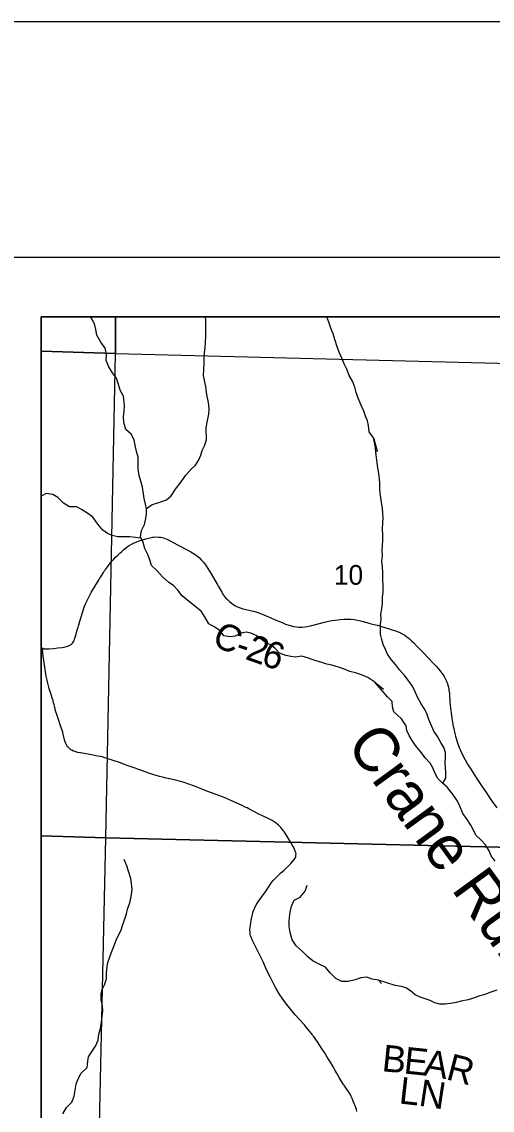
# Model space of a CAD drawing. Extents: x 0 to 34, y 0 to 22.
# Drawn here: x 1.59 to 2.589, y 19.687 to 22 of the extents above; entities that cross this region are included whole.
import ezdxf

# ---------------------------------------------------------------- set-up
doc = ezdxf.new("R2010")
doc.units = 0
for name, color, linetype in [('GM_X_Corporation', 7, 'Continuous'), ('GM_X_County_Road', 7, 'Continuous'), ('GM_X_County_Road_Text', 7, 'Continuous'), ('GM_X_Minor_River', 7, 'Continuous'), ('GM_X_Minor_River_Text', 7, 'Continuous'), ('GM_X_Section_Text', 7, 'Continuous'), ('GM_X_Township_Road', 7, 'Continuous'), ('GM_X_Township_Road_Text', 7, 'Continuous'), ('SH_Border', 7, 'Continuous'), ('SH_Cut_Line', 7, 'Continuous'), ('SH_Text', 7, 'Continuous')]:
    doc.layers.add(name, color=color, linetype=linetype)

msp = doc.modelspace()

# ---------------------------------------------------------------- linework, layer by layer
at = {"layer": 'GM_X_Corporation'}
for points in [[(8.4311, 21.3734), (1.6311, 21.3734), (1.6311, 16.1731), (2.3716, 16.1532), (2.3935, 16.1523), (3.7652, 16.1115), (4.1576, 16.1007)], [(4.7823, 18.128), (4.0508, 18.1454), (3.7812, 18.1547), (3.7776, 18.3354), (3.7807, 18.4204), (3.7875, 18.9248), (3.7889, 19.1658), (3.7877, 19.187), (3.1142, 19.2057), (2.7749, 19.2162), (2.7798, 20.0198), (2.7831, 20.242), (2.7976, 21.3075), (2.7987, 21.3734), (1.6311, 21.3734), (1.6311, 16.1731), (2.3716, 16.1532), (2.3935, 16.1523), (3.7652, 16.1115), (4.1576, 16.1007)]]:
    msp.add_lwpolyline(points, dxfattribs=at)
for points in [[(1.7887, 21.3734), (1.6311, 21.3734), (1.6311, 21.3003), (1.7888, 21.2952)], [(2.7987, 21.3734), (1.7887, 21.3734), (1.7888, 21.2952), (2.7974, 21.2696)], [(1.6311, 21.3003), (1.6311, 20.2706), (1.7685, 20.2662), (1.7888, 21.2952)], [(2.7974, 21.2696), (2.7815, 20.2421), (1.7685, 20.2662), (1.7888, 21.2952)], [(1.6311, 20.2706), (1.6311, 19.242), (1.7459, 19.2387), (1.7685, 20.2662)], [(2.7815, 20.2421), (2.7721, 19.2162), (1.7459, 19.2387), (1.7685, 20.2662)]]:
    msp.add_lwpolyline(points, close=True, dxfattribs=at)
at = {"layer": 'GM_X_County_Road'}
for points in [[(1.6344, 20.6688), (1.6351, 20.6685), (1.6371, 20.668), (1.6397, 20.6678), (1.6478, 20.6679), (1.6571, 20.6685), (1.6664, 20.6697), (1.6756, 20.6706), (1.6799, 20.6712), (1.6848, 20.6724), (1.689, 20.6738), (1.6919, 20.6752), (1.6945, 20.677), (1.6969, 20.6791), (1.699, 20.6816), (1.7004, 20.6838), (1.7012, 20.6855), (1.7021, 20.6883), (1.705, 20.6991), (1.7075, 20.708), (1.7087, 20.7116), (1.709, 20.7121), (1.7094, 20.7139), (1.7105, 20.7168), (1.7109, 20.7187), (1.7133, 20.7263), (1.7161, 20.7359), (1.7194, 20.7471), (1.7225, 20.7563), (1.7258, 20.7649), (1.7277, 20.7693), (1.7312, 20.7764), (1.737, 20.7872), (1.7448, 20.8003), (1.7539, 20.8148), (1.7549, 20.8163), (1.7559, 20.8179), (1.7578, 20.8209), (1.7597, 20.824), (1.7633, 20.8296), (1.7651, 20.8325), (1.7661, 20.8339), (1.7672, 20.8356), (1.7679, 20.8364), (1.772, 20.8421), (1.7726, 20.843), (1.774, 20.8448), (1.7754, 20.8466), (1.7768, 20.8485), (1.7793, 20.8517), (1.7821, 20.8549), (1.7853, 20.8585), (1.7892, 20.8624), (1.7935, 20.8669), (1.7982, 20.8713), (1.802, 20.8746), (1.806, 20.8781), (1.8091, 20.8808), (1.814, 20.8843), (1.8182, 20.887), (1.8231, 20.8901), (1.827, 20.8921), (1.8325, 20.8944), (1.8394, 20.8969), (1.8536, 20.9015), (1.8617, 20.9036), (1.8673, 20.9048), (1.8697, 20.9051), (1.8746, 20.9054), (1.8807, 20.9052), (1.8855, 20.9047), (1.8908, 20.9033), (1.8977, 20.9009), (1.9054, 20.8971), (1.9125, 20.8932), (1.9207, 20.8888), (1.9262, 20.8859), (1.9395, 20.8791), (1.9493, 20.8738), (1.9582, 20.8683), (1.9636, 20.8642), (1.9664, 20.8619), (1.9712, 20.8571), (1.9756, 20.852), (1.9801, 20.8461), (1.9853, 20.8384), (1.992, 20.8273), (2.0047, 20.8052), (2.0075, 20.8004), (2.0146, 20.7879), (2.0186, 20.7816), (2.0229, 20.7762), (2.0273, 20.7716), (2.031, 20.7682), (2.0354, 20.7647), (2.0405, 20.761), (2.0438, 20.7592), (2.0494, 20.7564), (2.0541, 20.7546), (2.0595, 20.7529), (2.0631, 20.7519), (2.0753, 20.7493), (2.0818, 20.7476), (2.0889, 20.7455), (2.0936, 20.7439), (2.1039, 20.7397), (2.1141, 20.7354), (2.1204, 20.7327), (2.1268, 20.7301), (2.1319, 20.7279), (2.1377, 20.7256), (2.1428, 20.7234), (2.1503, 20.7204), (2.1598, 20.7171), (2.167, 20.7151), (2.1733, 20.7142), (2.1783, 20.7139), (2.1846, 20.714), (2.1915, 20.7146), (2.1964, 20.7154), (2.2025, 20.7168), (2.2062, 20.7176), (2.2333, 20.7243), (2.2417, 20.7263), (2.2484, 20.7276), (2.2557, 20.7288), (2.2662, 20.7301), (2.2748, 20.7308), (2.2816, 20.731), (2.2889, 20.7308), (2.2963, 20.73), (2.3029, 20.7288), (2.3161, 20.7255), (2.3269, 20.7226), (2.3323, 20.7211), (2.3449, 20.7178), (2.3705, 20.7102), (2.3788, 20.7076), (2.3817, 20.7066), (2.3915, 20.7029), (2.3982, 20.6997), (2.4034, 20.6966), (2.4079, 20.6934), (2.4127, 20.6896), (2.4182, 20.6846), (2.4226, 20.6803), (2.4296, 20.6732), (2.4434, 20.6589), (2.4533, 20.6486), (2.4654, 20.6361), (2.4704, 20.6307), (2.4752, 20.625), (2.4802, 20.6187), (2.4842, 20.6133), (2.4872, 20.6086), (2.4902, 20.6033), (2.4923, 20.5988), (2.4945, 20.5931), (2.4959, 20.5885), (2.497, 20.5837), (2.4976, 20.58), (2.4984, 20.5727), (2.4997, 20.5541), (2.5007, 20.5423), (2.502, 20.5312), (2.5036, 20.5201), (2.5059, 20.5072), (2.508, 20.4975), (2.5103, 20.4878), (2.5117, 20.4824), (2.5131, 20.4769), (2.5157, 20.468), (2.5184, 20.4603), (2.5221, 20.4517), (2.5278, 20.4399), (2.5322, 20.4317), (2.5372, 20.423), (2.5454, 20.4098), (2.5563, 20.3931), (2.569, 20.374), (2.577, 20.3621), (2.5832, 20.3528), (2.5894, 20.3435), (2.5991, 20.3299)], [(1.6311, 20.671), (1.6333, 20.6694), (1.6344, 20.6688)]]:
    msp.add_lwpolyline(points, dxfattribs=at)
at = {"layer": 'GM_X_Minor_River'}
for points in [[(2.3398, 20.597), (2.325, 20.6071), (2.312, 20.6128), (2.2991, 20.6168), (2.2866, 20.6194), (2.2733, 20.625), (2.263, 20.6291), (2.2486, 20.6332), (2.2383, 20.6354), (2.225, 20.6391), (2.2125, 20.6432), (2.1988, 20.6481), (2.1848, 20.6518), (2.1707, 20.6501), (2.1613, 20.6516), (2.151, 20.6538), (2.1377, 20.6586), (2.1274, 20.6692), (2.1167, 20.6767), (2.1072, 20.682), (2.0973, 20.6887), (2.0878, 20.6963), (2.0768, 20.7011), (2.0673, 20.703), (2.0578, 20.7018), (2.0434, 20.6944), (2.0325, 20.6932), (2.0188, 20.6954), (2.0111, 20.706), (2.0001, 20.7135), (1.9875, 20.7206), (1.9795, 20.7343), (1.9707, 20.7479), (1.9432, 20.7697), (1.9303, 20.7802), (1.9215, 20.7923), (1.9119, 20.8021), (1.9024, 20.8085), (1.889, 20.8206), (1.8772, 20.8334), (1.8657, 20.8451), (1.8626, 20.8549), (1.8576, 20.8678), (1.8515, 20.8807), (1.848, 20.8936), (1.8422, 20.9057), (1.844, 20.919), (1.8507, 20.9319), (1.8533, 20.9444), (1.8548, 20.9543), (1.8547, 20.9653), (1.8527, 20.9752), (1.85, 20.9873), (1.8484, 20.9972), (1.8464, 21.0112), (1.8425, 21.0241), (1.839, 21.0362), (1.8367, 21.0491), (1.8373, 21.062), (1.8369, 21.0749), (1.8338, 21.087), (1.8306, 21.1007), (1.8287, 21.1117), (1.8225, 21.1238), (1.8107, 21.1336), (1.8064, 21.1484), (1.806, 21.1613), (1.8074, 21.1719), (1.8077, 21.1848), (1.806, 21.2045), (1.7991, 21.217), (1.7956, 21.2291), (1.791, 21.2431), (1.7826, 21.2541), (1.7749, 21.267), (1.7691, 21.2806), (1.7694, 21.2942), (1.7667, 21.3068), (1.7575, 21.3196), (1.749, 21.334), (1.7474, 21.3465), (1.7443, 21.3582), (1.737, 21.3707), (1.7358, 21.3734)], [(1.8547, 20.965), (1.857, 20.9672), (1.8668, 20.9745), (1.877, 20.9773), (1.8872, 20.9807), (1.8974, 20.9846), (1.9072, 20.993), (1.9162, 21.0071), (1.9286, 21.0224), (1.938, 21.0369), (1.9489, 21.0487), (1.9587, 21.0579), (1.9662, 21.069), (1.9699, 21.0789), (1.9729, 21.0891), (1.9777, 21.099), (1.9826, 21.1116), (1.9817, 21.1374), (1.9835, 21.1495), (1.9875, 21.1663), (1.9882, 21.1777), (1.9866, 21.1913), (1.9835, 21.2038), (1.9823, 21.2133), (1.9811, 21.2251), (1.9779, 21.238), (1.976, 21.2482), (1.9763, 21.2615), (1.9773, 21.274), (1.9776, 21.2839), (1.9783, 21.2976), (1.9794, 21.3071), (1.9804, 21.3188), (1.9811, 21.3321), (1.9809, 21.3651), (1.9801, 21.3734)], [(2.3374, 21.1163), (2.3279, 21.1287), (2.3266, 21.142), (2.3243, 21.1518), (2.32, 21.1624), (2.3166, 21.1727), (2.31, 21.1871), (2.3046, 21.2003), (2.3004, 21.2124), (2.2973, 21.2234), (2.293, 21.2351), (2.2857, 21.2488), (2.2803, 21.2616), (2.2749, 21.2734), (2.2699, 21.2855), (2.2641, 21.2983), (2.2599, 21.3097), (2.2556, 21.3226), (2.2517, 21.337), (2.2475, 21.3468), (2.2425, 21.362), (2.238, 21.3734)], [(2.4843, 20.3823), (2.4911, 20.3929), (2.4906, 20.4043), (2.4905, 20.4156), (2.4893, 20.4262), (2.4904, 20.4372), (2.4903, 20.4474), (2.4864, 20.458), (2.4803, 20.4689), (2.473, 20.4814), (2.4653, 20.493), (2.4588, 20.5077), (2.4545, 20.5179), (2.4502, 20.53), (2.4445, 20.5413), (2.4383, 20.5511), (2.431, 20.565), (2.426, 20.5763), (2.421, 20.5869), (2.413, 20.5986), (2.4038, 20.6102), (2.3923, 20.6233), (2.3836, 20.6342), (2.3744, 20.6451), (2.3671, 20.6564), (2.3625, 20.6666), (2.3579, 20.6772), (2.3551, 20.6874), (2.352, 20.6991), (2.3519, 20.7085), (2.3522, 20.7203), (2.3532, 20.7309), (2.3531, 20.7415), (2.3549, 20.7525), (2.356, 20.765), (2.3562, 20.7768), (2.358, 20.7889), (2.3579, 20.8026), (2.357, 20.8151), (2.3573, 20.8298), (2.3564, 20.8416), (2.3552, 20.8537), (2.3562, 20.8651), (2.3557, 20.8764), (2.356, 20.8867), (2.3571, 20.8988), (2.357, 20.9094), (2.3565, 20.9226), (2.3571, 20.9352), (2.3574, 20.9458), (2.3573, 20.956), (2.3565, 20.9666), (2.3545, 20.9783), (2.3525, 20.9889), (2.3513, 20.9987), (2.3504, 21.0086), (2.3503, 21.0192), (2.3499, 21.0298), (2.3483, 21.0404), (2.3466, 21.0525), (2.345, 21.0631), (2.3434, 21.0741), (2.3422, 21.0847), (2.3414, 21.0956), (2.3374, 21.1163), (2.3448, 21.0881), (2.3445, 21.0862)], [(1.843, 20.9039), (1.8411, 20.903), (1.8316, 20.9041), (1.8191, 20.9059), (1.7937, 20.9057), (1.7815, 20.9083), (1.772, 20.9128), (1.7621, 20.9199), (1.751, 20.9328), (1.7407, 20.9475), (1.7304, 20.9554), (1.7167, 20.9636), (1.7068, 20.9693), (1.6909, 20.9695), (1.6783, 20.9771), (1.6665, 20.9895), (1.6558, 20.9959), (1.6418, 20.9977), (1.6312, 20.9923), (1.6311, 20.9923)], [(2.463, 20.4149), (2.4576, 20.4247), (2.4469, 20.436), (2.4373, 20.4499), (2.4263, 20.4623), (2.4194, 20.4732), (2.4128, 20.4834), (2.4082, 20.4939), (2.4066, 20.5038), (2.397, 20.5188), (2.3806, 20.5342), (2.3772, 20.5444), (2.3767, 20.5557), (2.3671, 20.5659), (2.3398, 20.597), (2.3583, 20.5821), (2.3579, 20.5817)], [(2.5955, 20.2167), (2.5874, 20.2276), (2.5828, 20.2389), (2.5751, 20.2513), (2.566, 20.2615), (2.5546, 20.2716), (2.5499, 20.2825), (2.5442, 20.2934), (2.535, 20.3073), (2.5273, 20.3179), (2.52, 20.3356), (2.5146, 20.3462), (2.505, 20.3593), (2.4936, 20.3736), (2.4833, 20.3833), (2.4737, 20.3923), (2.4684, 20.4029), (2.463, 20.4149)], [(1.6769, 19.68), (1.6848, 19.693), (1.6961, 19.7045), (1.7013, 19.717), (1.7031, 19.7303), (1.7053, 19.7429), (1.709, 19.7528), (1.7157, 19.7661), (1.7289, 19.7779), (1.7304, 19.7916), (1.7314, 19.8011), (1.7382, 19.8106), (1.7461, 19.8232), (1.752, 19.8365), (1.7535, 19.8487), (1.7568, 19.8613), (1.7594, 19.8746), (1.7608, 19.8871), (1.7622, 19.8981), (1.7614, 19.9102), (1.7587, 19.922), (1.7586, 19.9345), (1.7604, 19.944), (1.7653, 19.9535), (1.7697, 19.9665), (1.7697, 19.979), (1.7715, 19.9919), (1.7729, 20.0014), (1.7759, 20.0109), (1.78, 20.0212), (1.7856, 20.0353), (1.7904, 20.0486), (1.7953, 20.0593), (1.8009, 20.0703), (1.8038, 20.0802), (1.8072, 20.0901), (1.812, 20.1049), (1.8142, 20.1148), (1.8194, 20.1281), (1.8224, 20.1418), (1.8246, 20.1563), (1.8226, 20.1691), (1.8214, 20.1801), (1.8163, 20.1953), (1.8132, 20.207), (1.8074, 20.2199)], [(2.3475, 19.9639), (2.3346, 19.9657), (2.3228, 19.9698), (2.3103, 19.969), (2.2979, 19.9644), (2.2835, 19.9608), (2.2702, 19.9611), (2.2573, 19.9675), (2.2451, 19.9796), (2.2351, 19.9916), (2.2214, 19.9976), (2.2089, 20.004), (2.1978, 20.0134), (2.1856, 20.0255), (2.1726, 20.0368), (2.1642, 20.0492), (2.1599, 20.0651), (2.1576, 20.0777), (2.1583, 20.0875), (2.159, 20.0978), (2.1604, 20.108), (2.163, 20.121), (2.1689, 20.1339), (2.1814, 20.1404), (2.1916, 20.153), (2.1964, 20.1656)], [(2.5994, 19.9428), (2.5862, 19.9385), (2.5738, 19.9331), (2.5632, 19.9307), (2.55, 19.9252), (2.5387, 19.9221), (2.5232, 19.9193), (2.5127, 19.9165), (2.501, 19.9145), (2.4896, 19.9129), (2.4779, 19.9131), (2.4673, 19.9157), (2.4574, 19.9205), (2.4468, 19.9242), (2.4362, 19.9275), (2.4256, 19.9323), (2.4157, 19.9409), (2.4058, 19.9472), (2.3963, 19.9505), (2.3831, 19.9523), (2.3475, 19.9639), (2.3539, 19.9565)]]:
    msp.add_lwpolyline(points, dxfattribs=at)
at = {"layer": 'GM_X_Township_Road'}
msp.add_lwpolyline([(2.302, 19.6845), (2.3011, 19.6893), (2.2998, 19.6929), (2.2963, 19.7015), (2.2943, 19.7065), (2.292, 19.7122), (2.2899, 19.7167), (2.2874, 19.7217), (2.2842, 19.7269), (2.2814, 19.731), (2.2785, 19.7351), (2.276, 19.7386), (2.2721, 19.7442), (2.2684, 19.7499), (2.2642, 19.7567), (2.2596, 19.7649), (2.2558, 19.772), (2.2538, 19.7758), (2.2509, 19.7807), (2.2455, 19.7897), (2.239, 19.8003), (2.2327, 19.8102), (2.2279, 19.8175), (2.218, 19.8326), (2.2095, 19.8448), (2.2084, 19.8463), (2.2076, 19.8473), (2.1986, 19.8592), (2.194, 19.8642), (2.1895, 19.8694), (2.1781, 19.8825), (2.1723, 19.889), (2.1674, 19.8946), (2.1586, 19.905), (2.1501, 19.9157), (2.1428, 19.9258), (2.1383, 19.9324), (2.1337, 19.9398), (2.1288, 19.9485), (2.1226, 19.9607), (2.1181, 19.9695), (2.1129, 19.9801), (2.1083, 19.9896), (2.1024, 20.0026), (2.0972, 20.0139), (2.0944, 20.0194), (2.0901, 20.0284), (2.0834, 20.041), (2.0793, 20.0494), (2.077, 20.0552), (2.076, 20.0581), (2.0752, 20.0611), (2.0748, 20.0648), (2.0747, 20.0697), (2.0754, 20.0765), (2.0758, 20.0796), (2.0773, 20.0913), (2.0784, 20.0974), (2.0799, 20.1035), (2.0817, 20.1094), (2.084, 20.1158), (2.088, 20.1235), (2.0923, 20.1304), (2.0991, 20.14), (2.1049, 20.148), (2.1075, 20.1515), (2.1103, 20.1556), (2.1127, 20.1592), (2.117, 20.1659), (2.1204, 20.1711), (2.124, 20.1754), (2.1282, 20.1799), (2.1303, 20.1822), (2.1357, 20.1873), (2.1404, 20.1919), (2.1466, 20.1971), (2.155, 20.2054), (2.1616, 20.2119), (2.1658, 20.2164), (2.1685, 20.2198), (2.1705, 20.223), (2.1719, 20.2262), (2.1724, 20.229), (2.1726, 20.2319), (2.1721, 20.2348), (2.171, 20.2381), (2.1696, 20.2414), (2.1678, 20.2453), (2.1644, 20.2515), (2.1616, 20.2561), (2.1532, 20.2705), (2.1479, 20.2784), (2.1439, 20.2838), (2.14, 20.2884), (2.1352, 20.2932), (2.1303, 20.2973), (2.1259, 20.3003), (2.1216, 20.3029), (2.1091, 20.3094), (2.1039, 20.3118), (2.0922, 20.3172), (2.0832, 20.3219), (2.0724, 20.3277), (2.0686, 20.3296), (2.0647, 20.3315), (2.0597, 20.3339), (2.0563, 20.3355), (2.0451, 20.3405), (2.0338, 20.3455), (2.031, 20.3467), (2.0247, 20.3494), (2.0161, 20.353), (2.0005, 20.359), (1.983, 20.3656), (1.9622, 20.3736), (1.9465, 20.3795), (1.9347, 20.3835), (1.927, 20.3858), (1.9168, 20.3885), (1.9101, 20.39), (1.901, 20.3921), (1.8962, 20.3932), (1.889, 20.3951), (1.8823, 20.3967), (1.868, 20.4009), (1.8598, 20.4037), (1.8521, 20.4062), (1.8404, 20.4103), (1.8375, 20.4113), (1.8305, 20.4139), (1.8223, 20.4168), (1.8153, 20.4194), (1.8066, 20.4227), (1.7973, 20.4261), (1.7821, 20.4314), (1.7715, 20.4349), (1.7661, 20.4364), (1.7602, 20.438), (1.7468, 20.4407), (1.7383, 20.4424), (1.7334, 20.4433), (1.731, 20.4437), (1.7255, 20.4448), (1.7188, 20.4458), (1.7145, 20.4466), (1.7133, 20.4469), (1.7091, 20.4477), (1.7049, 20.4488), (1.7031, 20.4494), (1.6996, 20.4506), (1.6962, 20.4521), (1.694, 20.4534), (1.6915, 20.4552), (1.6889, 20.4578), (1.687, 20.4598), (1.6855, 20.4623), (1.6845, 20.4643), (1.684, 20.4654), (1.6835, 20.4665), (1.6821, 20.47), (1.6807, 20.4747), (1.6778, 20.4861), (1.6767, 20.4909), (1.6716, 20.5062), (1.6682, 20.5156), (1.6667, 20.5196), (1.6639, 20.5285), (1.6624, 20.5339), (1.6617, 20.5363), (1.6604, 20.541), (1.6598, 20.5434), (1.6583, 20.5488), (1.6573, 20.553), (1.6564, 20.5565), (1.6561, 20.5577), (1.6546, 20.563), (1.6536, 20.5666), (1.6524, 20.5707), (1.6516, 20.573), (1.651, 20.5747), (1.6496, 20.5788), (1.6479, 20.5835), (1.6462, 20.5888), (1.6448, 20.5946), (1.6434, 20.6011), (1.6418, 20.6099), (1.6346, 20.6577), (1.6342, 20.6616), (1.634, 20.6644), (1.6341, 20.6662), (1.6343, 20.6678), (1.6344, 20.6688)], dxfattribs=at)
at = {"layer": 'SH_Border'}
msp.add_lwpolyline([(1.5, 21.5), (33.5, 21.5), (33.5, 0.5), (1.5, 0.5)], close=True, dxfattribs=at)
at = {"layer": 'SH_Cut_Line'}
msp.add_lwpolyline([(0, 0), (34, 0), (34, 22), (0, 22)], close=True, dxfattribs=at)
at = {"layer": 'SH_Text'}
for p, q in [((1.6311, 21.3734), (8.4311, 21.373)), ((1.6311, 14.5734), (1.6311, 21.3734))]:
    msp.add_line(p, q, dxfattribs=at)

# ---------------------------------------------------------------- texts
at = {"layer": 'GM_X_County_Road_Text'}
for s, rotation, p in [('C', 332.8712, (1.9908, 20.6789)), ('-', 341.1488, (2.0406, 20.6541)), ('2', 340.5258, (2.0625, 20.6466)), ('6', 340.9002, (2.0959, 20.6348))]:
    msp.add_text(s, height=0.0568, rotation=rotation, dxfattribs=at).set_placement(p)
at = {"layer": 'GM_X_Minor_River_Text'}
msp.add_text('Crane Run', height=0.09469, rotation=306.0663, dxfattribs=at).set_placement((2.2773, 20.4644))
at = {"layer": 'GM_X_Section_Text'}
msp.add_text('10', height=0.04186, rotation=0, dxfattribs=at).set_placement((2.2529, 20.8039))
at = {"layer": 'GM_X_Township_Road_Text'}
for s, rotation, p in [('B', 354.1038, (2.3535, 19.7706)), ('E', 354.1046, (2.4, 19.7658)), ('A', 350.6754, (2.4414, 19.7616)), ('R', 345.3854, (2.4893, 19.7537)), ('L', 353.6548, (2.3898, 19.702)), ('N', 351.2929, (2.4315, 19.6974))]:
    msp.add_text(s, height=0.0568, rotation=rotation, dxfattribs=at).set_placement(p)

doc.saveas('drawing.dxf')
